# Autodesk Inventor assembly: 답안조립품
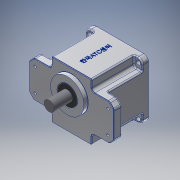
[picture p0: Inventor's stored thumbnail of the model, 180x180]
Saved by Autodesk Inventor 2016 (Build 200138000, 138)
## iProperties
Created: 2017-01
Part Number: 답안조립품
Material: 일반
Document SubType Name: Assembly
Designer: Owner
Author: Owner
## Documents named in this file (10)
- C:\Users\Owner\Desktop\470111V1015\답안조립품.iam
- C:\Users\Owner\Desktop\470111V1015\본체.ipt
- C:\Users\Owner\Desktop\470111V1015\커버.ipt
- C:\Users\Owner\Desktop\470111V1015\오일실 17 32 8.ipt
- C:\Users\Owner\Desktop\470111V1015\오일실 8 22 7.ipt
- C:\Users\Owner\Desktop\470111V1015\서브축.ipt
- C:\Users\Owner\Desktop\470111V1015\볼트 M4 x 10.ipt
- C:\Users\Owner\Desktop\470111V1015\베어링 6003.ipt
- C:\Users\Owner\Desktop\470111V1015\베어링 608.ipt
- C:\Users\Owner\Desktop\470111V1015\메인축.ipt
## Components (2 placed, 1 different names)
1. ISO 4762 M4 x 10:1
2. ISO 4762 M4 x 10:2
